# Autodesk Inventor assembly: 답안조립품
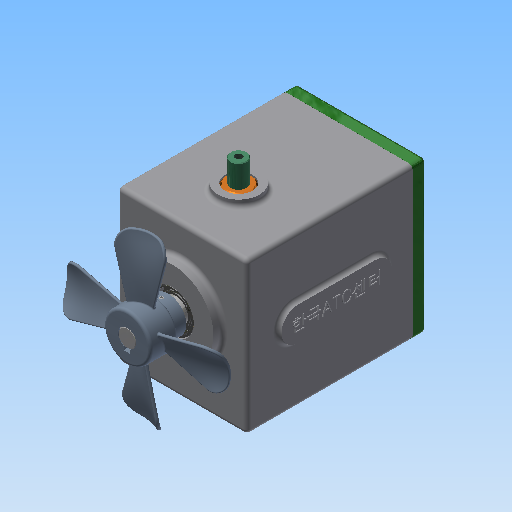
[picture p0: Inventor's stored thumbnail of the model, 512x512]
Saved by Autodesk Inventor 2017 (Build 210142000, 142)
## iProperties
Part Number: 답안조립품
Material: 일반
Document SubType Name: Assembly
Designer: MRC
Author: MRC
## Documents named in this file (17)
- C:\Users\MRC\Desktop\610205V1003\답안조립품.iam
- C:\Users\MRC\Desktop\610205V1003\본체.ipt
- C:\Users\MRC\Desktop\610205V1003\가변스프링.ipt
- C:\Users\MRC\Desktop\610205V1003\멈춤나사 M3x8.ipt
- C:\Users\MRC\Desktop\610205V1003\메인 기어 축.ipt
- C:\Users\MRC\Desktop\610205V1003\베어링 608.ipt
- C:\Users\MRC\Desktop\610205V1003\베어링 6903.ipt
- C:\Users\MRC\Desktop\610205V1003\볼트 M4 x 10.ipt
- C:\Users\MRC\Desktop\610205V1003\부시.ipt
- C:\Users\MRC\Desktop\610205V1003\서브 기어 축.ipt
- C:\Users\MRC\Desktop\610205V1003\슬라이더.ipt
- C:\Users\MRC\Desktop\610205V1003\오일 실 8 22 7.ipt
- C:\Users\MRC\Desktop\610205V1003\오일 실 17 30 8.ipt
- C:\Users\MRC\Desktop\610205V1003\커버.ipt
- C:\Users\MRC\Desktop\610205V1003\키 5 x 5 x 24.ipt
- C:\Users\MRC\Desktop\610205V1003\팬날개.ipt
- 팬날개.ipt
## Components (1 placed, 1 different names)
1. 가변스프링:1
